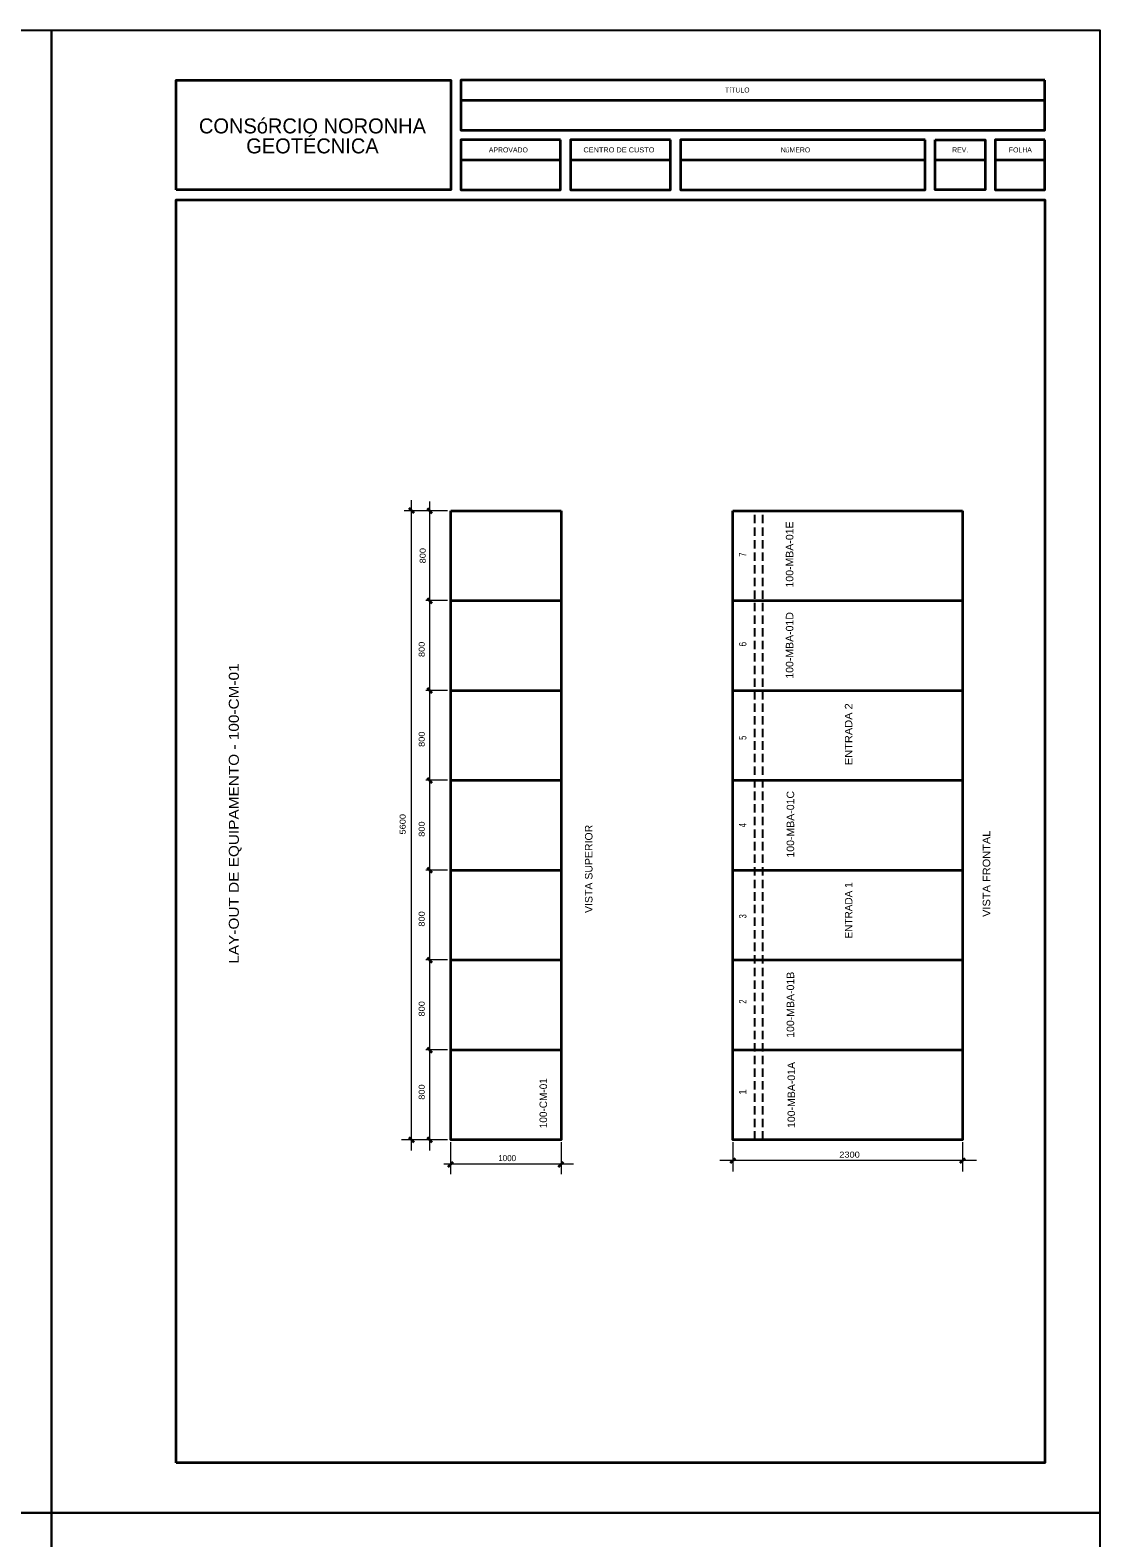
# Model space of a CAD drawing. Extents: x -4160 to -2690, y -474 to 714.
# Drawn here: x -2904 to -2689.8, y 412.5 to 714.5 of the extents above; entities that cross this region are included whole.
import ezdxf
from ezdxf.enums import TextEntityAlignment as Align

# ---------------------------------------------------------------- set-up
doc = ezdxf.new("R2010")
doc.units = 0
doc.header["$LTSCALE"] = 0.56
doc.linetypes.add('MEDIUM_DASHED', pattern=[4.5, 3, -1.5])
doc.layers.add('2', color=7, linetype='Continuous', lineweight=25)
doc.layers.add('5', color=7, linetype='Continuous', lineweight=35)

msp = doc.modelspace()

# ---------------------------------------------------------------- linework, layer by layer
at = {"layer": '2', "lineweight": 13}
for p, q in [((-2827.6858, 620.3628), (-2827.6859, 490.0799)), ((-2824.0332, 620.0392), (-2824.0333, 490.0799)), ((-2820.3987, 618.2288), (-2829.1137, 618.2288)), ((-2820.3987, 600.2288), (-2824.7832, 600.2288)), ((-2820.3987, 600.2288), (-2824.7832, 600.2288)), ((-2820.3987, 582.2288), (-2824.7832, 582.2288)), ((-2820.3987, 564.2288), (-2824.7832, 564.2288)), ((-2820.3987, 546.2288), (-2824.7832, 546.2288)), ((-2820.3987, 528.2288), (-2824.7832, 528.2288)), ((-2820.3988, 510.2288), (-2824.7832, 510.2288)), ((-2820.3988, 492.2288), (-2829.6464, 492.2288)), ((-2819.7992, 491.7099), (-2819.7992, 485.3576)), ((-2797.6712, 491.7098), (-2797.6712, 485.3575)), ((-2763.2477, 491.7098), (-2763.2477, 485.8828)), ((-2717.2477, 491.7098), (-2717.2477, 485.8828)), ((-2795.1964, 487.3054), (-2821.1812, 487.3055)), ((-2714.4619, 488.0716), (-2765.8742, 488.0716))]:
    msp.add_line(p, q, dxfattribs=at)
at = {"layer": '2', "lineweight": 35}
for p, q in [((-2828.1786, 618.8157), (-2827.193, 617.8155)), ((-2824.526, 618.7289), (-2823.5404, 617.7288)), ((-2819.7559, 618.2288), (-2797.6711, 618.2287)), ((-2763.2476, 618.2287), (-2717.2476, 618.2287)), ((-2763.2476, 618.2287), (-2717.2476, 618.2287)), ((-2824.526, 600.7289), (-2823.5404, 599.7288)), ((-2824.526, 600.7289), (-2823.5404, 599.7288)), ((-2819.7559, 600.2288), (-2797.6711, 600.2287)), ((-2763.2476, 600.2287), (-2717.2476, 600.2287)), ((-2824.526, 582.7289), (-2823.5404, 581.7288)), ((-2819.7559, 582.2288), (-2797.6711, 582.2287)), ((-2763.2476, 582.2287), (-2717.2476, 582.2287)), ((-2824.526, 564.7289), (-2823.5404, 563.7288)), ((-2819.7559, 564.2288), (-2797.6711, 564.2287)), ((-2763.2476, 564.2287), (-2717.2476, 564.2287)), ((-2824.526, 546.7289), (-2823.5404, 545.7288)), ((-2819.7559, 546.2288), (-2797.6711, 546.2287)), ((-2763.2476, 546.2287), (-2717.2476, 546.2287)), ((-2824.526, 528.7289), (-2823.5404, 527.7288)), ((-2819.7559, 528.2288), (-2797.6711, 528.2287)), ((-2763.2476, 528.2287), (-2717.2476, 528.2287)), ((-2824.526, 510.7289), (-2823.5404, 509.7288)), ((-2819.756, 510.2288), (-2797.6712, 510.2287)), ((-2763.2477, 510.2287), (-2717.2476, 510.2287)), ((-2828.1787, 492.7289), (-2827.1931, 491.7288)), ((-2824.5261, 492.7289), (-2823.5405, 491.7288)), ((-2820.2993, 486.8127), (-2819.2991, 487.7983)), ((-2798.1713, 486.8126), (-2797.1711, 487.7982)), ((-2763.7478, 487.5788), (-2762.7476, 488.5644)), ((-2717.7478, 487.5788), (-2716.7476, 488.5644))]:
    msp.add_line(p, q, dxfattribs=at)
at = {"layer": '2', "linetype": 'MEDIUM_DASHED'}
for p, q in [((-2758.8993, 492.2287), (-2758.8992, 618.2287)), ((-2757.2791, 492.2287), (-2757.279, 618.2287))]:
    msp.add_line(p, q, dxfattribs=at)
at = {"layer": '2', "lineweight": 35}
for points in [[(-2797.6711, 618.2287), (-2797.6712, 492.2287), (-2819.756, 492.2288), (-2819.7559, 618.2288)], [(-2717.2476, 618.2287), (-2717.2477, 492.2287), (-2763.2477, 492.2287), (-2763.2476, 618.2287)], [(-2819.7559, 600.2288), (-2819.7559, 600.2288), (-2797.6711, 600.2287)], [(-2763.2476, 600.2287), (-2763.2476, 600.2287), (-2717.2476, 600.2287)]]:
    msp.add_lwpolyline(points, dxfattribs=at)
at = {"layer": '5'}
for p, q in [((-2817.7642, 700.48), (-2700.7642, 700.48)), ((-2817.7642, 688.48), (-2797.7642, 688.48)), ((-2795.7642, 688.48), (-2775.7642, 688.48)), ((-2773.7642, 688.48), (-2724.7642, 688.48)), ((-2722.7642, 688.48), (-2712.7642, 688.48)), ((-2710.7642, 688.48), (-2700.7642, 688.48))]:
    msp.add_line(p, q, dxfattribs=at)
at = {"layer": '5', "lineweight": 25}
for points in [[(-2899.7642, 417.48), (-3109.7642, 417.48), (-3109.7642, 714.48), (-2899.7642, 714.48)], [(-2689.7642, 417.48), (-2899.7642, 417.48), (-2899.7642, 714.48), (-2689.7642, 714.48)], [(-2899.7642, 120.48), (-3109.7642, 120.48), (-3109.7642, 417.48), (-2899.7642, 417.48)], [(-2689.7642, 120.48), (-2899.7642, 120.48), (-2899.7642, 417.48), (-2689.7642, 417.48)]]:
    msp.add_lwpolyline(points, close=True, dxfattribs=at)
at = {"layer": '5'}
for points in [[(-2874.7642, 682.48), (-2874.7642, 704.48), (-2819.7642, 704.48), (-2819.7642, 682.48)], [(-2700.7642, 704.48), (-2817.7642, 704.48), (-2817.7642, 694.48), (-2700.7642, 694.48)], [(-2797.7642, 692.48), (-2817.7642, 692.48), (-2817.7642, 682.48), (-2797.7642, 682.48)], [(-2775.7642, 692.48), (-2795.7642, 692.48), (-2795.7642, 682.48), (-2775.7642, 682.48)], [(-2724.7642, 692.48), (-2773.7642, 692.48), (-2773.7642, 682.48), (-2724.7642, 682.48)], [(-2722.7642, 692.48), (-2712.7642, 692.48), (-2712.7642, 682.48), (-2722.7642, 682.48)], [(-2700.7642, 692.48), (-2710.7642, 692.48), (-2710.7642, 682.48), (-2700.7642, 682.48)], [(-2874.7642, 427.48), (-2874.7642, 680.48), (-2700.7642, 680.48), (-2700.7642, 427.48)]]:
    msp.add_lwpolyline(points, close=True, dxfattribs=at)

# ---------------------------------------------------------------- texts
at = {"layer": '2'}
for s, height, width, p in [('100-MBA-01E', 1.5, 1.05, (-2751.1608, 602.8399)), ('800', 1.2, 1.15, (-2824.797, 607.6725)), ('7', 1.5, 0.75, (-2760.5493, 609.0043)), ('100-MBA-01D', 1.5, 1.05, (-2751.1608, 584.5706)), ('800', 1.2, 1.15, (-2825, 588.9076)), ('6', 1.5, 0.85, (-2760.5493, 591.0043)), ('ENTRADA 2', 1.5, 1.1, (-2739.3396, 567.265)), ('800', 1.2, 1.15, (-2825, 570.9076)), ('5', 1.5, 0.75, (-2760.5493, 572.3146)), ('100-MBA-01C', 1.5, 1.05, (-2750.9895, 548.7403)), ('5600', 1.2, 1.15, (-2828.8153, 553.3647)), ('800', 1.2, 1.15, (-2825, 552.9076)), ('VISTA SUPERIOR', 1.5, 1.05, (-2791.387, 537.649)), ('4', 1.5, 0.75, (-2760.5493, 554.8023)), ('VISTA FRONTAL', 1.5, 1.1, (-2711.7246, 536.8564)), ('800', 1.2, 1.15, (-2825, 534.9076)), ('3', 1.5, 0.75, (-2760.5493, 536.5541)), ('100-MBA-01B', 1.5, 1.05, (-2750.9895, 512.644)), ('800', 1.2, 1.15, (-2825.0001, 516.9076)), ('2', 1.5, 0.75, (-2760.5493, 519.4832)), ('100-MBA-01A', 1.5, 1.05, (-2750.8178, 494.5736)), ('800', 1.2, 1.15, (-2825.0001, 500.2363))]:
    msp.add_text(s, height=height, rotation=90, dxfattribs=dict(at, width=width)).set_placement(p)
at = {"layer": '2', "width": 1.15}
msp.add_text('LAY-OUT DE EQUIPAMENTO - 100-CM-01', height=2, rotation=90, dxfattribs=at).set_placement((-2862.2231, 557.5583), align=Align.CENTER)
at = {"layer": '2'}
for s, p in [('ENTRADA 1', (-2739.3396, 532.5258)), ('100-CM-01', (-2800.4948, 494.5263)), ('1', (-2760.5494, 501.235))]:
    msp.add_text(s, height=1.5, rotation=90, dxfattribs=at).set_placement(p)
at = {"layer": '2', "width": 1.15}
msp.add_text('2300', height=1.2, dxfattribs=at).set_placement((-2741.9525, 488.6409))
at = {"layer": '2'}
msp.add_text('1000', height=1.2, dxfattribs=at).set_placement((-2810.2606, 487.9371))
at = {"layer": '5'}
for s, height, p in [('TíTULO', 1, (-2762.3847, 701.991)), ('CONSóRCIO NORONHA', 3, (-2847.4749, 693.7961)), ('GEOTÉCNICA', 3, (-2847.475, 689.7961)), ('APROVADO', 1, (-2808.2387, 689.9973)), ('REV.', 1, (-2717.7443, 689.9923)), ('FOLHA', 1, (-2705.6809, 689.9923))]:
    msp.add_text(s, height=height, dxfattribs=at).set_placement(p, align=Align.CENTER)
for s, width, p in [('CENTRO DE CUSTO', 1.1, (-2786.0934, 689.9973)), ('NúMERO', 0.95, (-2750.7227, 689.9923))]:
    msp.add_text(s, height=1, dxfattribs=dict(at, width=width)).set_placement(p, align=Align.CENTER)

doc.saveas('drawing.dxf')
